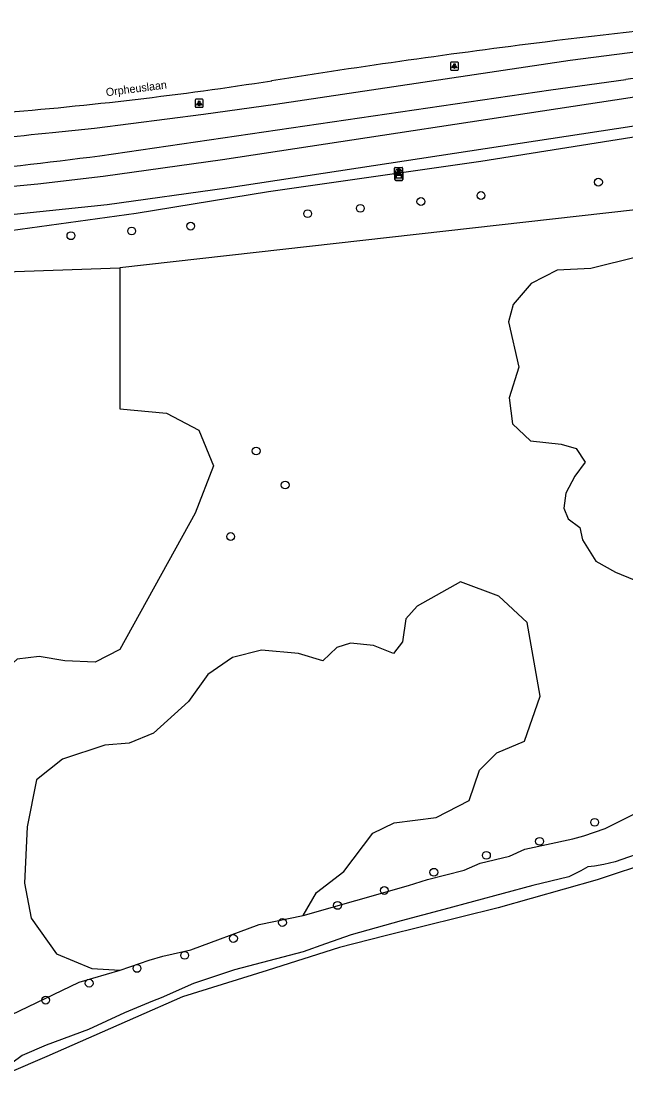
# Model space of a CAD drawing. Extents: x 161761 to 162722, y 384793 to 385405.
# Drawn here: x 162584.7 to 162660.3, y 385268.7 to 385400.2 of the extents above; entities that cross this region are included whole.
import ezdxf

# ---------------------------------------------------------------- set-up
doc = ezdxf.new("R2010")
doc.units = 0
for name, color, linetype in [('IMGEO_Boom', 7, 'Continuous'), ('IMGEO_Brandkraan', 7, 'Continuous'), ('IMGEO_Fietspad_gesloten', 7, 'Continuous'), ('IMGEO_Groenvoorziening', 7, 'Continuous'), ('IMGEO_Lichtpunt', 7, 'Continuous'), ('IMGEO_Loofbos', 7, 'Continuous'), ('IMGEO_Moeras', 7, 'Continuous'), ('IMGEO_Openbare_ruimte_label', 7, 'Continuous'), ('IMGEO_Rijbaan_lokaal_gesloten', 7, 'Continuous'), ('IMGEO_Verklikker', 7, 'Continuous'), ('IMGEO_Waterloop', 7, 'Continuous')]:
    doc.layers.add(name, color=color, linetype=linetype)

msp = doc.modelspace()

# ---------------------------------------------------------------- linework, layer by layer
at = {"layer": 'IMGEO_Boom'}
for centre in [(162656.82, 385380.03), (162634.65, 385377.61), (162642.15, 385378.36), (162620.5, 385376.09), (162627.09, 385376.77), (162605.89, 385374.54), (162590.94, 385373.34), (162598.52, 385373.93), (162614.07, 385346.45), (162617.7, 385342.2), (162610.89, 385335.76), (162656.35, 385300.06), (162649.47, 385297.68), (162642.83, 385295.93), (162636.27, 385293.82), (162630.08, 385291.55), (162624.24, 385289.68), (162617.36, 385287.54), (162611.24, 385285.55), (162605.15, 385283.44), (162599.19, 385281.81), (162593.22, 385279.96), (162587.79, 385277.85)]:
    msp.add_circle(centre, 0.489, dxfattribs=at)
at = {"layer": 'IMGEO_Brandkraan'}
for p, q in [((162631.36, 385380.94), (162631.36, 385381.8)), ((162631.44, 385381.87), (162632.29, 385381.87)), ((162631.85, 385381.65), (162631.87, 385381.65)), ((162632.36, 385381.8), (162632.36, 385380.94)), ((162632.29, 385380.87), (162631.44, 385380.87)), ((162631.87, 385381.09), (162631.85, 385381.09))]:
    msp.add_line(p, q, dxfattribs=at)
for points in [[(162631.36, 385380.94), (162631.36, 385381.8)], [(162631.44, 385381.87), (162632.29, 385381.87)], [(162631.71, 385381.57), (162631.71, 385381.17), (162631.92, 385381.17)], [(162631.94, 385381.57), (162631.71, 385381.57)], [(162632.36, 385381.8), (162632.36, 385380.94)], [(162632.29, 385380.87), (162631.44, 385380.87)], [(162631.89, 385381.49), (162631.83, 385381.49), (162631.83, 385381.41)], [(162631.83, 385381.41), (162631.89, 385381.41)], [(162631.9, 385381.34), (162631.83, 385381.34), (162631.83, 385381.26)], [(162631.83, 385381.26), (162631.9, 385381.26)]]:
    msp.add_lwpolyline(points, dxfattribs=at)
for centre, radius, start, end in [((162631.44, 385381.8), 0.0765, 91.552, 178.448), ((162631.44, 385381.8), 0.0765, 91.552, 178.448), ((162631.94, 385381.43), 0.145, 59.4692, 91.5367), ((162631.97, 385381.47), 0.0922, 285.5137, 58.1501), ((162632.29, 385381.8), 0.0765, 1.552, 88.448), ((162632.29, 385381.8), 0.0765, 1.552, 88.448), ((162631.44, 385380.95), 0.0765, 181.552, 268.448), ((162631.44, 385380.95), 0.0765, 181.552, 268.448), ((162631.89, 385381.45), 0.0379, 267.8285, 90.9355), ((162631.9, 385381.3), 0.0404, 269.8759, 90.5077), ((162631.93, 385381.42), 0.251, 268.6676, 293.5347), ((162631.97, 385381.28), 0.105, 301.3115, 78.989), ((162632.29, 385380.95), 0.0765, 271.552, 358.448), ((162632.29, 385380.95), 0.0765, 271.552, 358.448)]:
    msp.add_arc(centre, radius, start, end, dxfattribs=at)
for centre, major_axis, ratio, start_param, end_param in [((162631.85, 385381.37), (-0.387, 0.002), 0.722429, 4.712389, 7.853982), ((162631.87, 385381.37), (-0.39, 0.002), 0.717154, 1.570796, 4.712389)]:
    msp.add_ellipse(centre, major_axis=major_axis, ratio=ratio, start_param=start_param, end_param=end_param, dxfattribs=at)
at = {"layer": 'IMGEO_Fietspad_gesloten'}
for points in [[(162677.2, 385393.32), (162660.77, 385390.55), (162609.88, 385382.82), (162594.97, 385380.75), (162586.82, 385379.8), (162576.69, 385378.81)], [(162576.62, 385375.27), (162595.45, 385377.23), (162610.41, 385379.33), (162660.98, 385387.04), (162677.7, 385389.81)]]:
    msp.add_lwpolyline(points, dxfattribs=at)
at = {"layer": 'IMGEO_Groenvoorziening'}
msp.add_lwpolyline([(162663.21, 385296.62), (162658.92, 385295.14), (162657.48, 385294.78), (162656.33, 385294.6), (162655.51, 385294.48), (162654.61, 385293.98), (162653.13, 385293.25), (162648.61, 385292.16), (162637.52, 385289.17), (162632.19, 385287.77), (162625.95, 385285.99), (162622.73, 385284.88), (162619.95, 385283.88), (162611.37, 385281.64), (162606.23, 385279.92), (162602.23, 385278.15), (162601.14, 385277.7), (162597.63, 385276.25), (162593.13, 385274.17), (162587.86, 385272.22), (162584.87, 385270.93), (162583.57, 385269.99)], dxfattribs=at)
at = {"layer": 'IMGEO_Lichtpunt'}
for p, q in [((162638.34, 385394.93), (162638.34, 385394.13)), ((162638.34, 385394.93), (162638.34, 385394.13)), ((162639.24, 385395.03), (162638.43, 385395.03)), ((162639.24, 385395.03), (162638.43, 385395.03)), ((162639.34, 385394.13), (162639.34, 385394.93)), ((162639.34, 385394.13), (162639.34, 385394.93)), ((162638.43, 385394.03), (162639.24, 385394.03)), ((162638.43, 385394.03), (162639.24, 385394.03)), ((162606.46, 385390.29), (162606.46, 385389.48)), ((162606.46, 385390.29), (162606.46, 385389.48)), ((162607.36, 385390.38), (162606.55, 385390.38)), ((162607.36, 385390.38), (162606.55, 385390.38)), ((162607.45, 385389.48), (162607.45, 385390.29)), ((162607.45, 385389.48), (162607.45, 385390.29)), ((162606.55, 385389.39), (162607.36, 385389.39)), ((162606.55, 385389.39), (162607.36, 385389.39))]:
    msp.add_line(p, q, dxfattribs=at)
for points in [[(162638.71, 385394.6), (162638.75, 385394.57), (162638.56, 385394.31), (162638.53, 385394.34), (162638.71, 385394.6)], [(162638.81, 385394.55), (162638.86, 385394.55), (162638.86, 385394.23), (162638.81, 385394.23), (162638.81, 385394.55)], [(162638.92, 385394.57), (162638.96, 385394.6), (162639.15, 385394.33), (162639.11, 385394.31), (162638.92, 385394.57)], [(162606.83, 385389.95), (162606.87, 385389.92), (162606.68, 385389.66), (162606.64, 385389.69), (162606.83, 385389.95)], [(162606.93, 385389.9), (162606.98, 385389.9), (162606.98, 385389.58), (162606.93, 385389.58), (162606.93, 385389.9)], [(162607.04, 385389.92), (162607.08, 385389.95), (162607.27, 385389.69), (162607.23, 385389.66), (162607.04, 385389.92)]]:
    msp.add_lwpolyline(points, dxfattribs=at)
for centre in [(162638.84, 385394.73), (162606.96, 385390.09)]:
    msp.add_circle(centre, 0.0994, dxfattribs=at)
for centre, start, end in [((162638.43, 385394.93), 90, 180), ((162638.43, 385394.93), 90, 180), ((162639.24, 385394.93), 0, 90), ((162639.24, 385394.93), 0, 90), ((162638.43, 385394.13), 180, 270), ((162638.43, 385394.13), 180, 270), ((162639.24, 385394.13), 270, 0), ((162639.24, 385394.13), 270, 360), ((162606.55, 385390.29), 90, 180), ((162606.55, 385390.29), 90, 180), ((162606.55, 385389.48), 180, 270), ((162606.55, 385389.48), 180, 270), ((162607.36, 385390.29), 0, 90), ((162607.36, 385390.29), 0, 90), ((162607.36, 385389.48), 270, 0), ((162607.36, 385389.48), 270, 360)]:
    msp.add_arc(centre, 0.0946, start, end, dxfattribs=at)
at = {"layer": 'IMGEO_Loofbos'}
for points in [[(162539.75, 385367.33), (162547.53, 385371.52), (162564.34, 385372.34), (162582.17, 385373.84), (162599.09, 385376.16), (162615.6, 385378.86), (162642.13, 385382.64), (162662.81, 385385.95)], [(162671.44, 385377.68), (162597.03, 385369.31)], [(162661.74, 385370.7), (162655.86, 385369.23), (162651.66, 385369.04), (162648.43, 385367.38), (162646.18, 385364.73), (162645.59, 385362.58), (162646.86, 385356.91), (162645.69, 385353.09), (162646.08, 385349.86), (162648.33, 385347.71), (162652.15, 385347.32), (162654.05, 385346.78), (162655.18, 385345.07), (162653.86, 385343.3), (162652.73, 385341.2), (162652.49, 385339.29), (162653.03, 385337.97), (162654.49, 385336.9), (162654.84, 385335.33), (162656.5, 385332.69), (162658.95, 385331.32), (162661.3, 385330.34)], [(162563.71, 385368.16), (162597.03, 385369.31)], [(162619.93, 385288.42), (162621.59, 385291.29), (162625.04, 385293.92), (162628.66, 385298.69), (162631.29, 385300.01), (162636.55, 385300.67), (162640.67, 385302.8), (162641.98, 385306.59), (162644.12, 385308.73), (162647.57, 385310.21), (162649.55, 385315.8), (162647.9, 385325.01), (162644.37, 385328.3), (162639.6, 385330.11), (162634.17, 385327.06), (162632.77, 385325.5), (162632.36, 385322.62), (162631.21, 385321.14), (162628.74, 385322.13), (162625.86, 385322.46), (162624.14, 385321.88), (162622.41, 385320.24), (162619.37, 385321.14), (162614.76, 385321.55), (162611.14, 385320.65), (162608.02, 385318.51), (162605.63, 385315.14), (162601.27, 385311.19), (162598.23, 385309.96), (162595.19, 385309.71), (162589.88, 385307.95), (162586.65, 385305.36), (162585.46, 385299.51), (162585.15, 385292.45), (162585.99, 385288.08), (162589.13, 385283.65), (162593.56, 385281.79), (162597.07, 385281.57)], [(162597.07, 385281.57), (162600.73, 385282.86), (162602.43, 385283.34), (162605.93, 385284.15), (162614.46, 385287.31), (162619.93, 385288.42)]]:
    msp.add_lwpolyline(points, dxfattribs=at)
at = {"layer": 'IMGEO_Moeras'}
for points in [[(162597.03, 385369.31), (162597.03, 385351.7), (162602.86, 385351.19), (162606.93, 385349.04), (162608.74, 385344.58), (162606.44, 385338.7), (162597.03, 385321.64), (162593.97, 385320.05), (162590.2, 385320.22), (162586.97, 385320.79), (162584.23, 385320.45), (162581.6, 385318.07), (162576.17, 385307.82), (162559.86, 385291.41)], [(162619.93, 385288.42), (162633.12, 385292.18), (162635.48, 385292.9), (162640.05, 385294.09), (162642.07, 385294.97), (162645.73, 385295.83), (162647.61, 385296.71), (162653.62, 385297.99), (162654.99, 385298.37), (162657.65, 385299.27), (162661.58, 385301.26), (162663.33, 385301.89), (162667.4, 385304.47), (162669.55, 385305.61), (162671.33, 385307.11), (162676.69, 385304.86)], [(162581.73, 385275.47), (162583.47, 385275.99), (162591.95, 385280.08), (162597.07, 385281.57)]]:
    msp.add_lwpolyline(points, dxfattribs=at)
at = {"layer": 'IMGEO_Rijbaan_lokaal_gesloten'}
for points in [[(162588.63, 385386.24), (162593.87, 385386.79), (162607.51, 385388.51), (162616.48, 385389.77), (162653.28, 385395.26), (162662.03, 385396.41), (162671.16, 385397.6), (162683.89, 385399.1)], [(162594.54, 385383.33), (162650.87, 385391.57), (162660.26, 385392.85)]]:
    msp.add_lwpolyline(points, dxfattribs=at)
for centre, radius, start, end in [((162801.26, 384169.62), 1237.18, 95.93611, 97.01473), ((162773.54, 384402.58), 1002.57, 97.06834, 99.04015), ((162736.2, 384879.22), 519.22, 95.7299, 98.4107), ((162545.11, 385847.7), 460.49, 274.5738, 278.8573), ((162547.84, 385772.3), 388.21, 273.9316, 276.0323), ((162534.96, 385832.51), 453.11, 275.0346, 277.5557)]:
    msp.add_arc(centre, radius, start, end, dxfattribs=at)
at = {"layer": 'IMGEO_Verklikker'}
for p, q in [((162631.4, 385380.35), (162631.4, 385381.15)), ((162631.4, 385381.15), (162631.4, 385380.35)), ((162631.5, 385381.25), (162632.29, 385381.25)), ((162632.29, 385381.25), (162631.5, 385381.25)), ((162632.29, 385380.25), (162631.5, 385380.25)), ((162631.5, 385380.25), (162632.29, 385380.25)), ((162632.39, 385381.15), (162632.39, 385380.35)), ((162632.39, 385380.35), (162632.39, 385381.15))]:
    msp.add_line(p, q, dxfattribs=at)
for points in [[(162631.5, 385380.98), (162632.29, 385380.98), (162632.29, 385380.52), (162631.5, 385380.52), (162631.5, 385380.98)], [(162631.57, 385380.92), (162631.57, 385380.58), (162632.23, 385380.58), (162632.23, 385380.92), (162631.57, 385380.92)]]:
    msp.add_lwpolyline(points, dxfattribs=at)
for centre, start, end in [((162631.5, 385381.15), 90, 180), ((162631.5, 385381.15), 90, 180), ((162631.5, 385380.35), 180, 270), ((162631.5, 385380.35), 180, 270), ((162632.29, 385381.15), 0, 90), ((162632.29, 385381.15), 360, 90), ((162632.29, 385380.35), 270, 0), ((162632.29, 385380.35), 270, 0)]:
    msp.add_arc(centre, 0.1, start, end, dxfattribs=at)
at = {"layer": 'IMGEO_Waterloop'}
msp.add_lwpolyline([(162663.68, 385295.19), (162656.68, 385292.89), (162644.31, 385289.38), (162630.2, 385285.87), (162624.47, 385284.41), (162615.44, 385281.54), (162604.87, 385278.28), (162599.02, 385275.69), (162587.94, 385270.79), (162583.18, 385268.75)], dxfattribs=at)

# ---------------------------------------------------------------- texts
at = {"layer": 'IMGEO_Openbare_ruimte_label'}
msp.add_text('Orpheuslaan', height=1, rotation=7.3524, dxfattribs=at).set_placement((162595.37, 385390.76))

doc.saveas('drawing.dxf')
